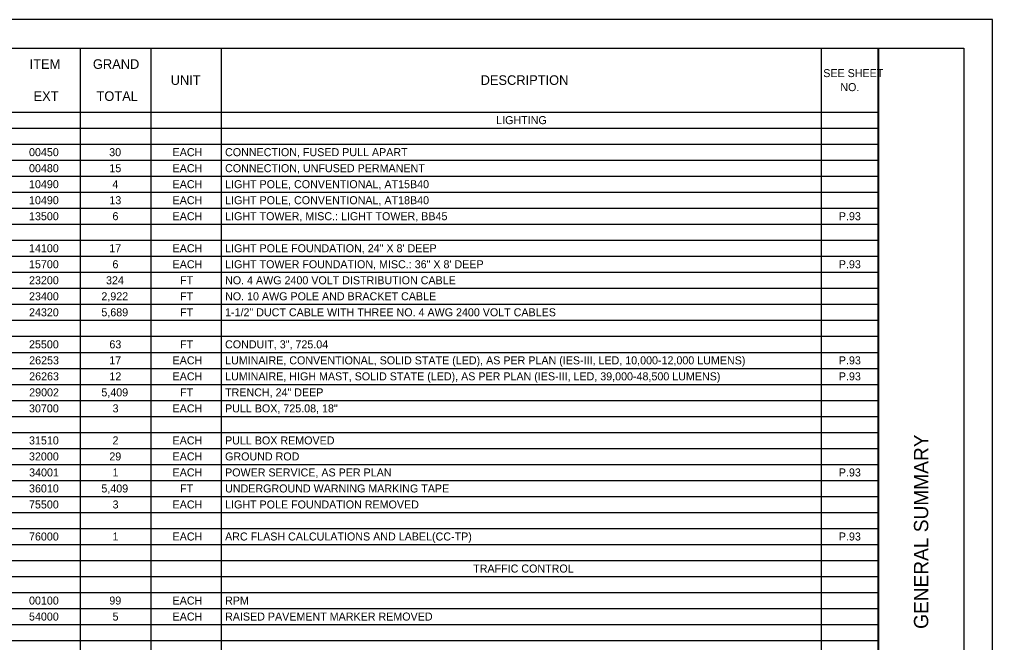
# Model space of a CAD drawing. Extents: x 0 to 34, y 0 to 22.
# Drawn here: x 16.98 to 34, y 11.11 to 22 of the extents above; entities that cross this region are included whole.
import ezdxf

# ---------------------------------------------------------------- set-up
doc = ezdxf.new("R2010")
doc.units = 0
for name, color, linetype in [('SH_Border', 7, 'Continuous'), ('SH_Cut_Line', 7, 'Continuous'), ('SH_Data', 7, 'Continuous'), ('SH_Text', 7, 'Continuous')]:
    doc.layers.add(name, color=color, linetype=linetype)

msp = doc.modelspace()

# ---------------------------------------------------------------- linework, layer by layer
at = {"layer": 'SH_Border'}
msp.add_line((32, 0.5), (32, 21.5), dxfattribs=at)
msp.add_lwpolyline([(1.5, 21.5), (33.5, 21.5), (33.5, 0.5), (1.5, 0.5)], close=True, dxfattribs=at)
at = {"layer": 'SH_Cut_Line'}
msp.add_lwpolyline([(0, 0), (34, 0), (34, 22), (0, 22)], close=True, dxfattribs=at)
at = {"layer": 'SH_Text'}
for p, q in [((1.5, 21.5), (32.004, 21.5)), ((18.036, 21.5), (18.036, 0.5)), ((19.272, 21.5), (19.272, 0.5)), ((20.507, 21.5), (20.507, 0.5)), ((30.999, 21.5), (30.999, 0.5)), ((32.004, 21.5), (32.004, 0.5)), ((1.5, 20.38), (32.004, 20.38)), ((1.5, 20.1), (32.004, 20.1)), ((1.5, 19.82), (32.004, 19.82)), ((1.5, 19.54), (32.004, 19.54)), ((1.5, 19.26), (32.004, 19.26)), ((1.5, 18.98), (32.004, 18.98)), ((1.5, 18.7), (32.004, 18.7)), ((1.5, 18.42), (32.004, 18.42)), ((1.5, 18.14), (32.004, 18.14)), ((1.5, 17.86), (32.004, 17.86)), ((1.5, 17.58), (32.004, 17.58)), ((1.5, 17.3), (32.004, 17.3)), ((1.5, 17.02), (32.004, 17.02)), ((1.5, 16.74), (32.004, 16.74)), ((1.5, 16.46), (32.004, 16.46)), ((1.5, 16.18), (32.004, 16.18)), ((1.5, 15.9), (32.004, 15.9)), ((1.5, 15.62), (32.004, 15.62)), ((1.5, 15.34), (32.004, 15.34)), ((1.5, 15.06), (32.004, 15.06)), ((1.5, 14.78), (32.004, 14.78)), ((1.5, 14.5), (32.004, 14.5)), ((1.5, 14.22), (32.004, 14.22)), ((1.5, 13.94), (32.004, 13.94)), ((1.5, 13.66), (32.004, 13.66)), ((1.5, 13.38), (32.004, 13.38)), ((1.5, 13.1), (32.004, 13.1)), ((1.5, 12.82), (32.004, 12.82)), ((1.5, 12.54), (32.004, 12.54)), ((1.5, 12.26), (32.004, 12.26)), ((1.5, 11.98), (32.004, 11.98)), ((1.5, 11.7), (32.004, 11.7)), ((1.5, 11.42), (32.004, 11.42)), ((1.5, 11.14), (32.004, 11.14))]:
    msp.add_line(p, q, dxfattribs=at)

# ---------------------------------------------------------------- texts
at = {"layer": 'SH_Data'}
msp.add_text('GENERAL SUMMARY', height=0.25, rotation=90, dxfattribs=at).set_placement((32.875, 11.344))
at = {"layer": 'SH_Text'}
for s, height, p in [('ITEM', 0.168, (17.154, 21.136)), ('GRAND', 0.168, (18.261, 21.136)), ('SEE SHEET ', 0.14, (31.038, 20.992)), ('UNIT', 0.168, (19.622, 20.856)), ('DESCRIPTION', 0.168, (25.044, 20.856)), ('NO.', 0.14, (31.337, 20.747)), ('EXT', 0.168, (17.222, 20.576)), ('TOTAL', 0.168, (18.324, 20.576)), ('LIGHTING', 0.14, (25.317, 20.17)), ('00450', 0.14, (17.143, 19.61)), ('30', 0.14, (18.546, 19.61)), ('EACH', 0.14, (19.655, 19.61)), ('CONNECTION, FUSED PULL APART', 0.14, (20.573, 19.61)), ('00480', 0.14, (17.143, 19.33)), ('15', 0.14, (18.549, 19.33)), ('EACH', 0.14, (19.655, 19.33)), ('CONNECTION, UNFUSED PERMANENT', 0.14, (20.573, 19.33)), ('10490', 0.14, (17.143, 19.05)), ('4', 0.14, (18.601, 19.05)), ('EACH', 0.14, (19.655, 19.05)), ('LIGHT POLE, CONVENTIONAL, AT15B40', 0.14, (20.573, 19.05)), ('10490', 0.14, (17.143, 18.77)), ('13', 0.14, (18.549, 18.77)), ('EACH', 0.14, (19.655, 18.77)), ('LIGHT POLE, CONVENTIONAL, AT18B40', 0.14, (20.573, 18.77)), ('13500', 0.14, (17.143, 18.49)), ('6', 0.14, (18.603, 18.49)), ('EACH', 0.14, (19.655, 18.49)), ('LIGHT TOWER, MISC.: LIGHT TOWER, BB45', 0.14, (20.573, 18.49)), ('P.93', 0.14, (31.311, 18.49)), ('14100', 0.14, (17.143, 17.93)), ('17', 0.14, (18.547, 17.93)), ('EACH', 0.14, (19.655, 17.93)), ('LIGHT POLE FOUNDATION, 24" X 8\' DEEP', 0.14, (20.573, 17.93)), ('15700', 0.14, (17.143, 17.65)), ('6', 0.14, (18.603, 17.65)), ('EACH', 0.14, (19.655, 17.65)), ('LIGHT TOWER FOUNDATION, MISC.: 36" X 8\' DEEP', 0.14, (20.573, 17.65)), ('P.93', 0.14, (31.311, 17.65)), ('23200', 0.14, (17.143, 17.37)), ('324', 0.14, (18.49, 17.37)), ('FT', 0.14, (19.786, 17.37)), ('NO. 4 AWG 2400 VOLT DISTRIBUTION CABLE', 0.14, (20.573, 17.37)), ('23400', 0.14, (17.143, 17.09)), ('2,922', 0.14, (18.409, 17.09)), ('FT', 0.14, (19.786, 17.09)), ('NO. 10 AWG POLE AND BRACKET CABLE', 0.14, (20.573, 17.09)), ('24320', 0.14, (17.143, 16.81)), ('5,689', 0.14, (18.409, 16.81)), ('FT', 0.14, (19.786, 16.81)), ('1-1/2" DUCT CABLE WITH THREE NO. 4 AWG 2400 VOLT CABLES', 0.14, (20.573, 16.81)), ('25500', 0.14, (17.143, 16.25)), ('63', 0.14, (18.549, 16.25)), ('FT', 0.14, (19.786, 16.25)), ('CONDUIT, 3", 725.04', 0.14, (20.573, 16.25)), ('26253', 0.14, (17.146, 15.97)), ('17', 0.14, (18.547, 15.97)), ('EACH', 0.14, (19.655, 15.97)), ('LUMINAIRE, CONVENTIONAL, SOLID STATE (LED), AS PER PLAN (IES-III, LED, 10,000-12,000 LUMENS)', 0.14, (20.573, 15.97)), ('P.93', 0.14, (31.311, 15.97)), ('LUMINAIRE, HIGH MAST, SOLID STATE (LED), AS PER PLAN (IES-III, LED, 39,000-48,500 LUMENS)', 0.14, (20.573, 15.69)), ('26263', 0.14, (17.146, 15.69)), ('12', 0.14, (18.549, 15.69)), ('EACH', 0.14, (19.655, 15.69)), ('P.93', 0.14, (31.311, 15.69)), ('29002', 0.14, (17.146, 15.41)), ('5,409', 0.14, (18.409, 15.41)), ('FT', 0.14, (19.786, 15.41)), ('TRENCH, 24" DEEP', 0.14, (20.573, 15.41)), ('30700', 0.14, (17.143, 15.13)), ('3', 0.14, (18.605, 15.13)), ('EACH', 0.14, (19.655, 15.13)), ('PULL BOX, 725.08, 18"', 0.14, (20.573, 15.13)), ('31510', 0.14, (17.143, 14.57)), ('2', 0.14, (18.604, 14.57)), ('EACH', 0.14, (19.655, 14.57)), ('PULL BOX REMOVED', 0.14, (20.573, 14.57)), ('32000', 0.14, (17.143, 14.29)), ('29', 0.14, (18.548, 14.29)), ('EACH', 0.14, (19.655, 14.29)), ('GROUND ROD', 0.14, (20.573, 14.29)), ('34001', 0.14, (17.145, 14.01)), ('1', 0.14, (18.604, 14.01)), ('EACH', 0.14, (19.655, 14.01)), ('POWER SERVICE, AS PER PLAN', 0.14, (20.573, 14.01)), ('P.93', 0.14, (31.311, 14.01)), ('36010', 0.14, (17.143, 13.73)), ('5,409', 0.14, (18.409, 13.73)), ('FT', 0.14, (19.786, 13.73)), ('UNDERGROUND WARNING MARKING TAPE', 0.14, (20.573, 13.73)), ('75500', 0.14, (17.143, 13.45)), ('3', 0.14, (18.605, 13.45)), ('EACH', 0.14, (19.655, 13.45)), ('LIGHT POLE FOUNDATION REMOVED', 0.14, (20.573, 13.45)), ('76000', 0.14, (17.143, 12.89)), ('1', 0.14, (18.604, 12.89)), ('EACH', 0.14, (19.655, 12.89)), ('ARC FLASH CALCULATIONS AND LABEL(CC-TP)', 0.14, (20.573, 12.89)), ('P.93', 0.14, (31.311, 12.89)), ('TRAFFIC CONTROL', 0.14, (24.914, 12.33)), ('00100', 0.14, (17.143, 11.77)), ('99', 0.14, (18.548, 11.77)), ('EACH', 0.14, (19.655, 11.77)), ('RPM', 0.14, (20.573, 11.77)), ('54000', 0.14, (17.143, 11.49)), ('5', 0.14, (18.605, 11.49)), ('EACH', 0.14, (19.655, 11.49)), ('RAISED PAVEMENT MARKER REMOVED', 0.14, (20.573, 11.49))]:
    msp.add_text(s, height=height, dxfattribs=at).set_placement(p)

doc.saveas('drawing.dxf')
